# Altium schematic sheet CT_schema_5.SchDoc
size 143 x 123 mm
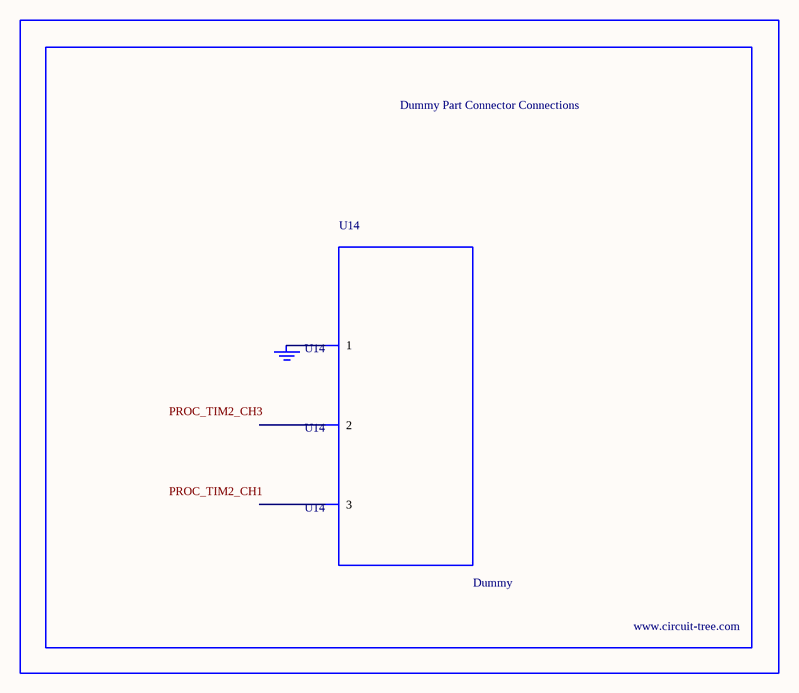
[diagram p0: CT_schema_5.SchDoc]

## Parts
BORDER4  (no value)
GND_INSTANCE_4_0  (no value)
U14  Dummy  [DUMMY_PACKAGE_125]

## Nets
NetGND_INSTANCE_4_0_0: GND_INSTANCE_4_0.0(GND) U14.1

Not connected (* = marked no-connect by the designer): U14 2 3

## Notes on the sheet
- Labels drawn without touching a wire or pin: PROC_TIM2_CH1, PROC_TIM2_CH3

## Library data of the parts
BORDER4 = BORDER_PAGE4
GND_INSTANCE_4_0 = GND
